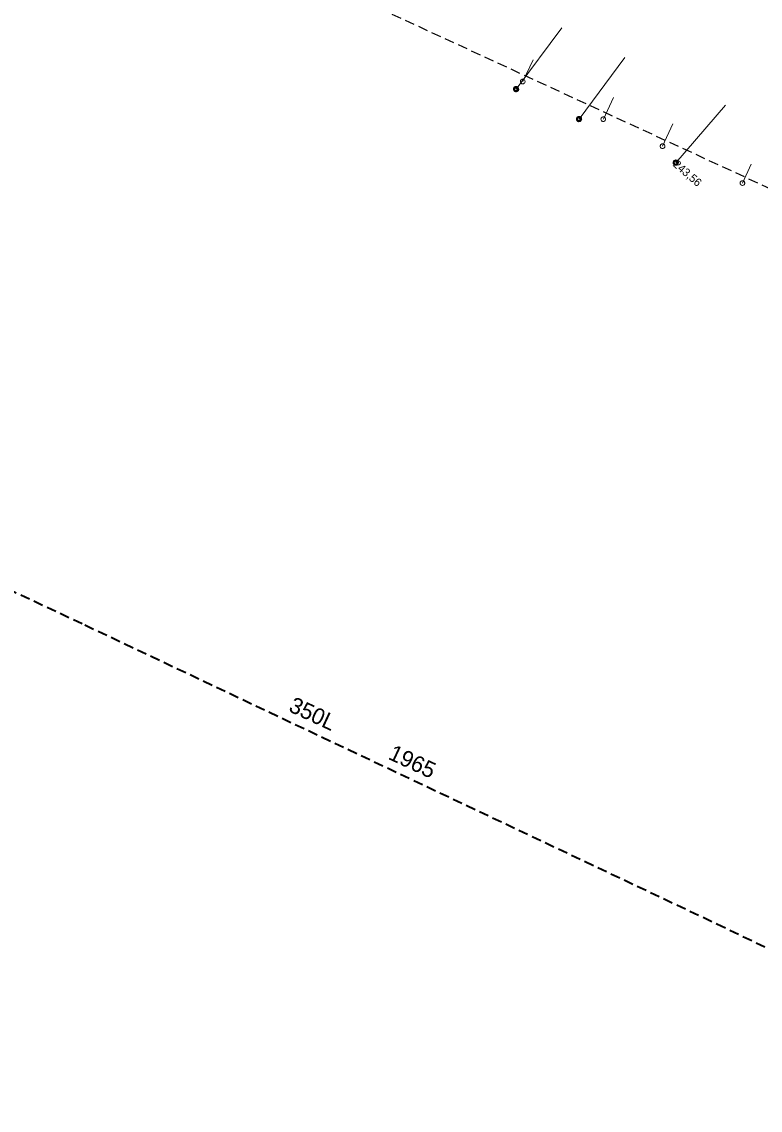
# Model space of a CAD drawing. Extents: x -735085 to -733500, y -1044153 to -1043402.
# Drawn here: x -734443.8 to -734370.7, y -1043798.1 to -1043690.4 of the extents above; entities that cross this region are included whole.
import ezdxf

# ---------------------------------------------------------------- set-up
doc = ezdxf.new("R2010")
doc.units = 0
doc.header["$LTSCALE"] = 0.32
doc.linetypes.add('MEDIUM_DASHED', pattern=[4.5, 3, -1.5])
doc.layers.add('15', color=7, linetype='Continuous')
doc.layers.add('16', color=7, linetype='Continuous')
for name, color, linetype, lineweight in [('18', 7, 'Continuous', 13), ('49', 7, 'Continuous', 13), ('63', 7, 'MEDIUM_DASHED', 25), ('8', 7, 'Continuous', 13)]:
    doc.layers.add(name, color=color, linetype=linetype, lineweight=lineweight)

msp = doc.modelspace()

# ---------------------------------------------------------------- linework, layer by layer
at = {"layer": '18'}
for points in [[(-734394.602, -1043697.028), (-734394.608, -1043696.972), (-734394.625, -1043696.919), (-734394.654, -1043696.87), (-734394.692, -1043696.829), (-734394.738, -1043696.797), (-734394.79, -1043696.775), (-734394.845, -1043696.764), (-734394.901, -1043696.766), (-734394.956, -1043696.779), (-734395.007, -1043696.804), (-734395.051, -1043696.839), (-734395.087, -1043696.882), (-734395.112, -1043696.932), (-734395.127, -1043696.987), (-734395.13, -1043697.043), (-734395.121, -1043697.098), (-734395.1, -1043697.151), (-734395.069, -1043697.197), (-734395.029, -1043697.236), (-734394.981, -1043697.266), (-734394.928, -1043697.285), (-734394.872, -1043697.292), (-734394.816, -1043697.288), (-734394.762, -1043697.271), (-734394.713, -1043697.244), (-734394.671, -1043697.206), (-734394.638, -1043697.161), (-734394.615, -1043697.11), (-734394.603, -1043697.055)], [(-734394.661, -1043697.031), (-734394.667, -1043696.982), (-734394.685, -1043696.936), (-734394.713, -1043696.895), (-734394.75, -1043696.862), (-734394.794, -1043696.84), (-734394.842, -1043696.828), (-734394.891, -1043696.828), (-734394.939, -1043696.84), (-734394.983, -1043696.863), (-734395.02, -1043696.896), (-734395.048, -1043696.937), (-734395.065, -1043696.984), (-734395.071, -1043697.033), (-734395.064, -1043697.082), (-734395.046, -1043697.128), (-734395.018, -1043697.168), (-734394.981, -1043697.201), (-734394.937, -1043697.223), (-734394.888, -1043697.235), (-734394.839, -1043697.234), (-734394.791, -1043697.222), (-734394.748, -1043697.198), (-734394.711, -1043697.165), (-734394.683, -1043697.124), (-734394.667, -1043697.077)], [(-734394.72, -1043697.035), (-734394.726, -1043696.993), (-734394.743, -1043696.955), (-734394.771, -1043696.924), (-734394.806, -1043696.901), (-734394.846, -1043696.89), (-734394.888, -1043696.89), (-734394.928, -1043696.902), (-734394.963, -1043696.925), (-734394.99, -1043696.957), (-734395.007, -1043696.995), (-734395.012, -1043697.036), (-734395.006, -1043697.078), (-734394.988, -1043697.115), (-734394.96, -1043697.147), (-734394.924, -1043697.169), (-734394.884, -1043697.18), (-734394.842, -1043697.179), (-734394.802, -1043697.166), (-734394.768, -1043697.143), (-734394.741, -1043697.11), (-734394.725, -1043697.072)], [(-734388.369, -1043699.987), (-734388.375, -1043699.931), (-734388.392, -1043699.878), (-734388.421, -1043699.829), (-734388.459, -1043699.788), (-734388.505, -1043699.756), (-734388.557, -1043699.734), (-734388.612, -1043699.723), (-734388.668, -1043699.725), (-734388.723, -1043699.738), (-734388.774, -1043699.763), (-734388.818, -1043699.798), (-734388.854, -1043699.841), (-734388.879, -1043699.891), (-734388.894, -1043699.946), (-734388.897, -1043700.002), (-734388.888, -1043700.057), (-734388.867, -1043700.11), (-734388.836, -1043700.156), (-734388.796, -1043700.195), (-734388.748, -1043700.225), (-734388.695, -1043700.244), (-734388.639, -1043700.251), (-734388.583, -1043700.247), (-734388.529, -1043700.23), (-734388.48, -1043700.203), (-734388.438, -1043700.165), (-734388.405, -1043700.12), (-734388.382, -1043700.069), (-734388.37, -1043700.014)], [(-734388.428, -1043699.99), (-734388.434, -1043699.941), (-734388.452, -1043699.895), (-734388.48, -1043699.854), (-734388.517, -1043699.821), (-734388.561, -1043699.799), (-734388.609, -1043699.787), (-734388.658, -1043699.787), (-734388.706, -1043699.799), (-734388.75, -1043699.822), (-734388.787, -1043699.855), (-734388.815, -1043699.896), (-734388.832, -1043699.943), (-734388.838, -1043699.992), (-734388.831, -1043700.041), (-734388.813, -1043700.087), (-734388.785, -1043700.127), (-734388.748, -1043700.16), (-734388.704, -1043700.182), (-734388.655, -1043700.194), (-734388.606, -1043700.193), (-734388.558, -1043700.181), (-734388.515, -1043700.157), (-734388.478, -1043700.124), (-734388.45, -1043700.083), (-734388.434, -1043700.036)], [(-734388.487, -1043699.994), (-734388.493, -1043699.952), (-734388.51, -1043699.914), (-734388.538, -1043699.883), (-734388.573, -1043699.86), (-734388.613, -1043699.849), (-734388.655, -1043699.849), (-734388.695, -1043699.861), (-734388.73, -1043699.884), (-734388.757, -1043699.916), (-734388.774, -1043699.954), (-734388.779, -1043699.995), (-734388.773, -1043700.037), (-734388.755, -1043700.074), (-734388.727, -1043700.106), (-734388.691, -1043700.128), (-734388.651, -1043700.139), (-734388.609, -1043700.138), (-734388.569, -1043700.125), (-734388.535, -1043700.102), (-734388.508, -1043700.069), (-734388.492, -1043700.031)], [(-734378.797, -1043704.308), (-734378.803, -1043704.252), (-734378.82, -1043704.199), (-734378.848, -1043704.15), (-734378.887, -1043704.109), (-734378.933, -1043704.077), (-734378.985, -1043704.055), (-734379.04, -1043704.044), (-734379.096, -1043704.046), (-734379.151, -1043704.059), (-734379.201, -1043704.084), (-734379.246, -1043704.119), (-734379.282, -1043704.162), (-734379.307, -1043704.212), (-734379.322, -1043704.267), (-734379.325, -1043704.323), (-734379.316, -1043704.378), (-734379.295, -1043704.431), (-734379.264, -1043704.477), (-734379.223, -1043704.516), (-734379.176, -1043704.546), (-734379.123, -1043704.565), (-734379.067, -1043704.572), (-734379.011, -1043704.568), (-734378.956, -1043704.551), (-734378.907, -1043704.524), (-734378.866, -1043704.486), (-734378.833, -1043704.441), (-734378.809, -1043704.39), (-734378.798, -1043704.335)], [(-734378.856, -1043704.311), (-734378.862, -1043704.262), (-734378.88, -1043704.216), (-734378.907, -1043704.175), (-734378.945, -1043704.142), (-734378.989, -1043704.12), (-734379.037, -1043704.108), (-734379.086, -1043704.108), (-734379.134, -1043704.12), (-734379.178, -1043704.143), (-734379.215, -1043704.176), (-734379.243, -1043704.217), (-734379.26, -1043704.264), (-734379.266, -1043704.313), (-734379.259, -1043704.362), (-734379.241, -1043704.408), (-734379.213, -1043704.448), (-734379.176, -1043704.481), (-734379.132, -1043704.503), (-734379.083, -1043704.515), (-734379.034, -1043704.514), (-734378.986, -1043704.502), (-734378.943, -1043704.478), (-734378.906, -1043704.445), (-734378.878, -1043704.404), (-734378.862, -1043704.357)], [(-734378.915, -1043704.315), (-734378.921, -1043704.273), (-734378.938, -1043704.235), (-734378.966, -1043704.204), (-734379, -1043704.181), (-734379.041, -1043704.17), (-734379.083, -1043704.17), (-734379.123, -1043704.182), (-734379.157, -1043704.205), (-734379.184, -1043704.237), (-734379.201, -1043704.275), (-734379.206, -1043704.316), (-734379.201, -1043704.358), (-734379.183, -1043704.395), (-734379.155, -1043704.427), (-734379.119, -1043704.449), (-734379.079, -1043704.46), (-734379.037, -1043704.459), (-734378.997, -1043704.446), (-734378.963, -1043704.423), (-734378.936, -1043704.39), (-734378.92, -1043704.352)]]:
    msp.add_lwpolyline(points, close=True, dxfattribs=at)
at = {"layer": '49'}
for p, q in [((-734394.866, -1043697.041), (-734390.318, -1043690.954)), ((-734394.866, -1043697.041), (-734390.318, -1043690.954)), ((-734388.633, -1043700), (-734384.083, -1043693.912)), ((-734388.633, -1043700), (-734384.083, -1043693.912)), ((-734379.061, -1043704.321), (-734374.146, -1043698.623)), ((-734379.061, -1043704.321), (-734374.146, -1043698.623))]:
    msp.add_line(p, q, dxfattribs=at)
at = {"layer": '63'}
msp.add_lwpolyline([(-734957.565, -1043435.501), (-734250.468, -1043761.931)], dxfattribs=at)
at = {"layer": '8'}
for p, q in [((-734393.17, -1043694.13), (-734394.193, -1043696.287)), ((-734385.21, -1043697.86), (-734386.223, -1043700.008)), ((-734379.36, -1043700.47), (-734380.357, -1043702.688)), ((-734371.579, -1043704.46), (-734372.45, -1043706.337))]:
    msp.add_line(p, q, dxfattribs=at)
for points in [[(-734394.103, -1043696.073), (-734394.153, -1043696.056), (-734394.206, -1043696.051), (-734394.257, -1043696.058), (-734394.307, -1043696.076), (-734394.351, -1043696.105), (-734394.387, -1043696.144), (-734394.413, -1043696.189), (-734394.429, -1043696.238), (-734394.433, -1043696.291), (-734394.425, -1043696.344), (-734394.405, -1043696.392), (-734394.375, -1043696.435), (-734394.335, -1043696.47), (-734394.29, -1043696.495), (-734394.239, -1043696.51), (-734394.187, -1043696.512), (-734394.135, -1043696.503), (-734394.086, -1043696.482), (-734394.045, -1043696.45), (-734394.011, -1043696.41), (-734393.986, -1043696.364), (-734393.973, -1043696.313), (-734393.973, -1043696.26), (-734393.983, -1043696.208), (-734394.005, -1043696.162), (-734394.038, -1043696.12), (-734394.079, -1043696.087)], [(-734386.134, -1043699.794), (-734386.184, -1043699.777), (-734386.237, -1043699.772), (-734386.289, -1043699.779), (-734386.338, -1043699.798), (-734386.382, -1043699.827), (-734386.417, -1043699.866), (-734386.444, -1043699.911), (-734386.46, -1043699.961), (-734386.463, -1043700.013), (-734386.454, -1043700.066), (-734386.434, -1043700.114), (-734386.404, -1043700.157), (-734386.364, -1043700.192), (-734386.318, -1043700.217), (-734386.268, -1043700.231), (-734386.215, -1043700.233), (-734386.164, -1043700.224), (-734386.115, -1043700.202), (-734386.074, -1043700.171), (-734386.04, -1043700.13), (-734386.016, -1043700.084), (-734386.003, -1043700.033), (-734386.003, -1043699.98), (-734386.014, -1043699.928), (-734386.036, -1043699.881), (-734386.069, -1043699.84), (-734386.11, -1043699.807)], [(-734380.272, -1043702.472), (-734380.322, -1043702.457), (-734380.375, -1043702.453), (-734380.427, -1043702.46), (-734380.476, -1043702.48), (-734380.519, -1043702.51), (-734380.554, -1043702.549), (-734380.58, -1043702.595), (-734380.594, -1043702.645), (-734380.597, -1043702.698), (-734380.587, -1043702.75), (-734380.566, -1043702.798), (-734380.535, -1043702.84), (-734380.495, -1043702.874), (-734380.449, -1043702.898), (-734380.398, -1043702.912), (-734380.345, -1043702.912), (-734380.294, -1043702.902), (-734380.246, -1043702.88), (-734380.205, -1043702.848), (-734380.172, -1043702.807), (-734380.149, -1043702.76), (-734380.137, -1043702.709), (-734380.137, -1043702.656), (-734380.149, -1043702.604), (-734380.173, -1043702.558), (-734380.206, -1043702.517), (-734380.247, -1043702.485)], [(-734372.362, -1043706.123), (-734372.412, -1043706.106), (-734372.464, -1043706.101), (-734372.516, -1043706.108), (-734372.566, -1043706.127), (-734372.609, -1043706.157), (-734372.645, -1043706.195), (-734372.671, -1043706.24), (-734372.687, -1043706.29), (-734372.69, -1043706.343), (-734372.681, -1043706.395), (-734372.661, -1043706.444), (-734372.631, -1043706.486), (-734372.591, -1043706.521), (-734372.545, -1043706.546), (-734372.494, -1043706.56), (-734372.442, -1043706.562), (-734372.39, -1043706.552), (-734372.342, -1043706.531), (-734372.301, -1043706.499), (-734372.267, -1043706.459), (-734372.243, -1043706.413), (-734372.23, -1043706.361), (-734372.23, -1043706.308), (-734372.241, -1043706.257), (-734372.264, -1043706.21), (-734372.296, -1043706.168), (-734372.337, -1043706.136)]]:
    msp.add_lwpolyline(points, close=True, dxfattribs=at)
at = {"layer": '8', "linetype": 'MEDIUM_DASHED', "lineweight": 35}
msp.add_lwpolyline([(-734536.445, -1043703.656), (-734437.539, -1043750.071), (-734375.002, -1043779.659), (-734325.456, -1043803.606), (-734187.217, -1043868.148)], dxfattribs=at)

# ---------------------------------------------------------------- texts
at = {"layer": '15'}
for s, p in [('350L', (-734417.473, -1043758.581)), ('1965', (-734407.61, -1043763.313))]:
    msp.add_text(s, height=1.6, rotation=335, dxfattribs=at).set_placement(p)
at = {"layer": '16'}
msp.add_text('243,56', height=0.8, rotation=319, dxfattribs=at).set_placement((-734379.394, -1043704.591))

doc.saveas('drawing.dxf')
